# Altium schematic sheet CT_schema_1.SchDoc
size 544 x 512 mm
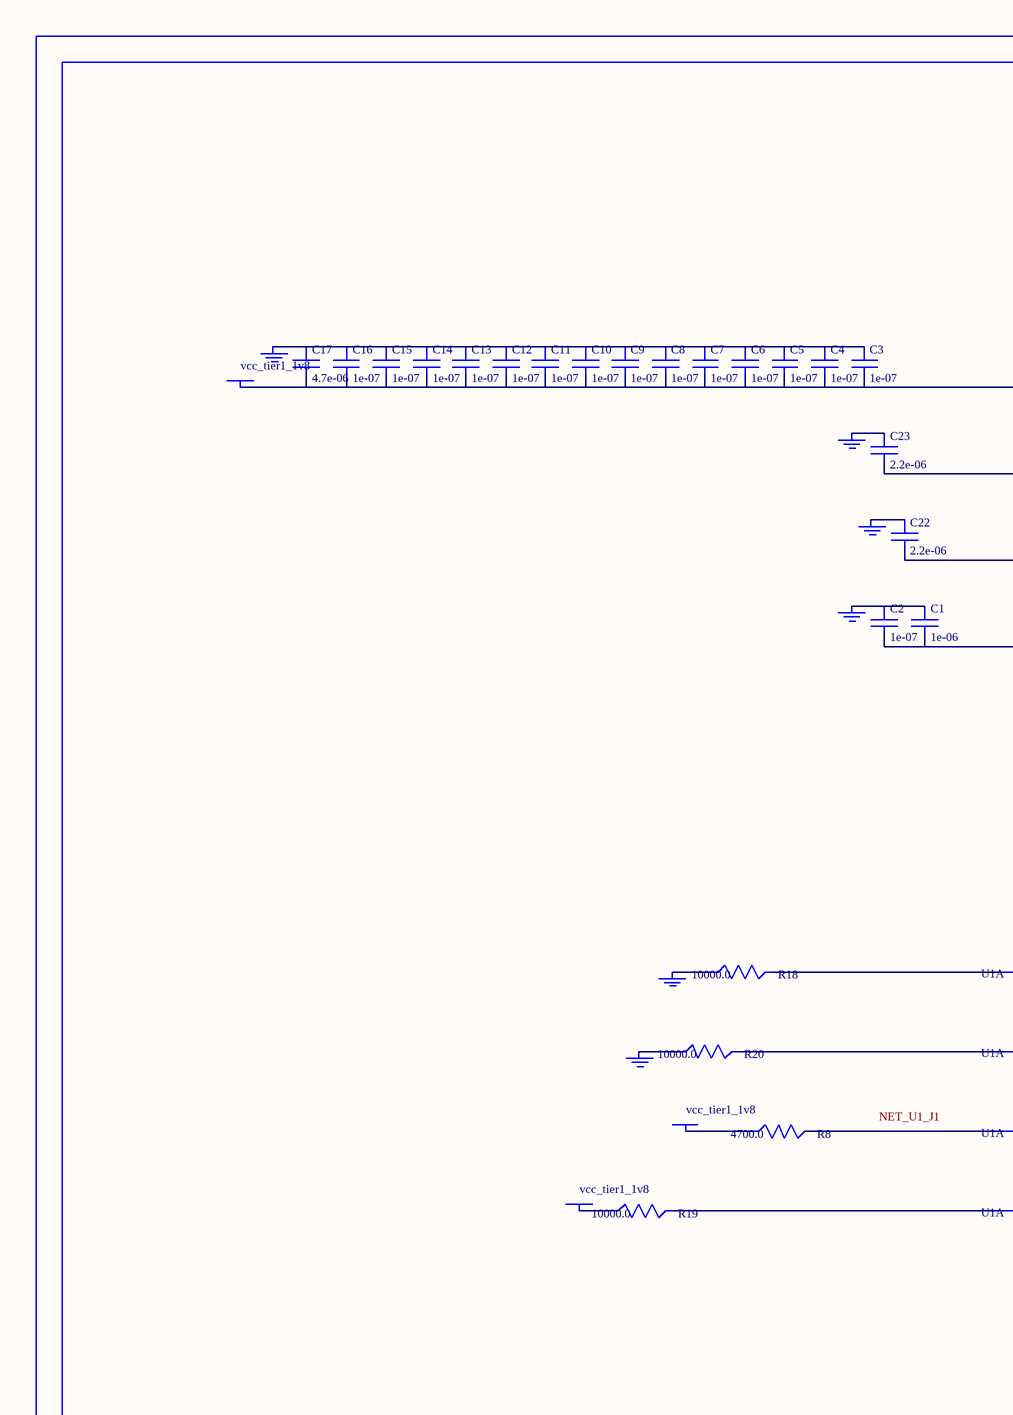
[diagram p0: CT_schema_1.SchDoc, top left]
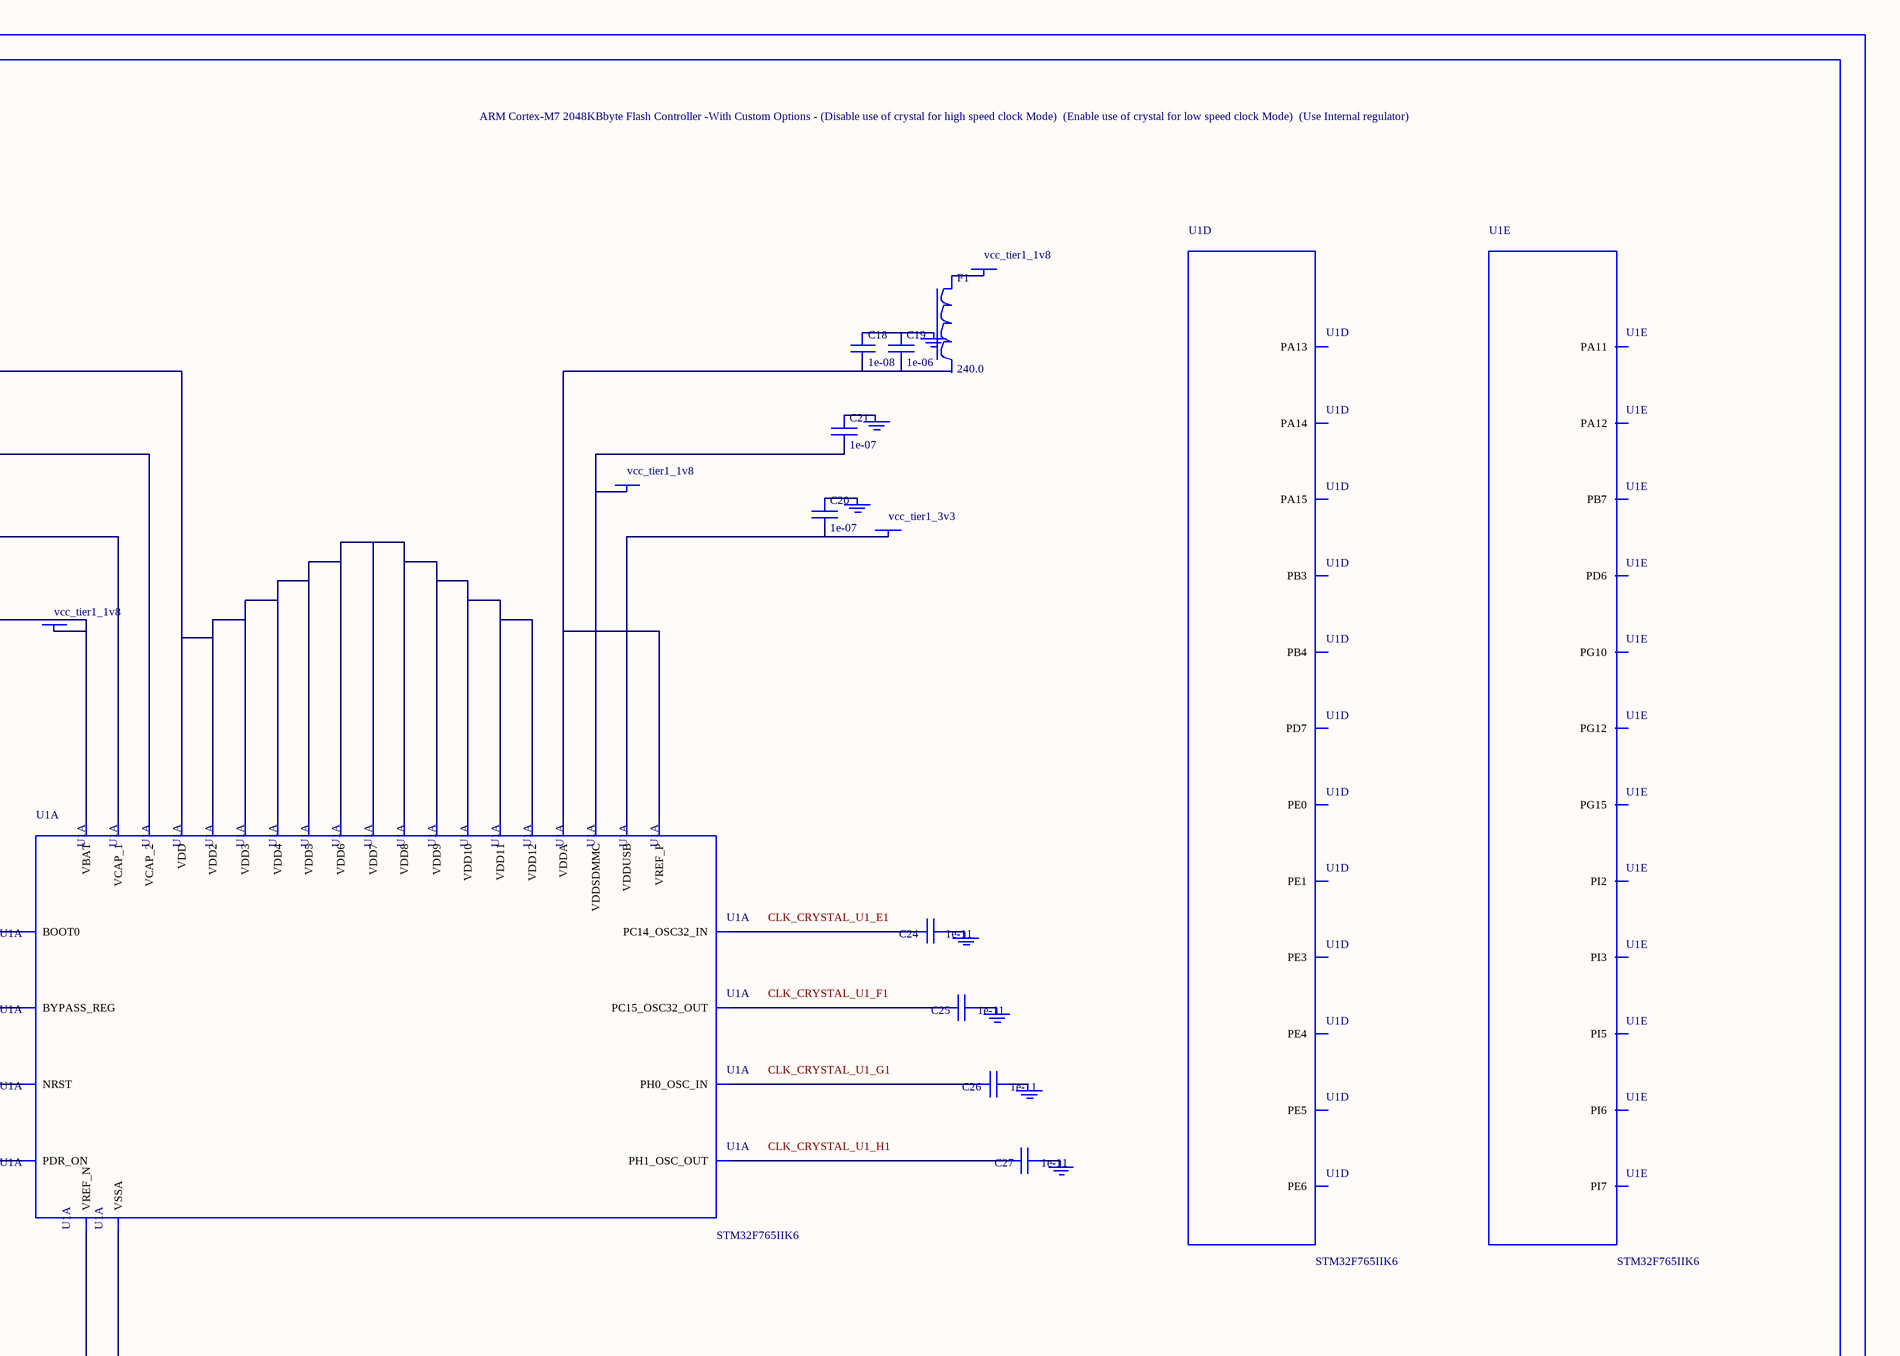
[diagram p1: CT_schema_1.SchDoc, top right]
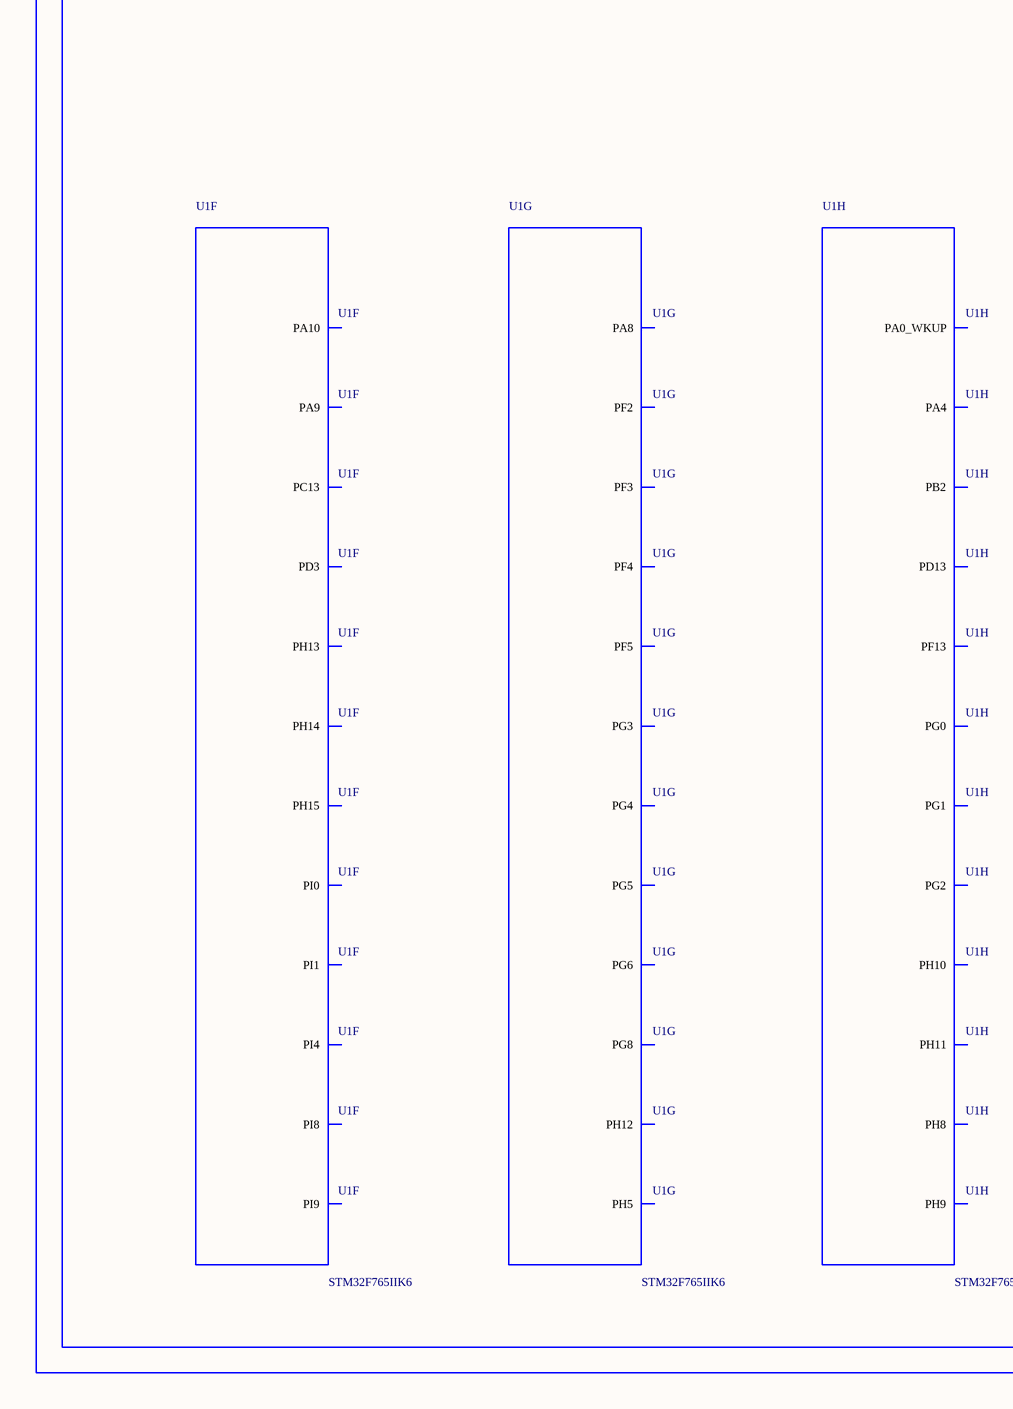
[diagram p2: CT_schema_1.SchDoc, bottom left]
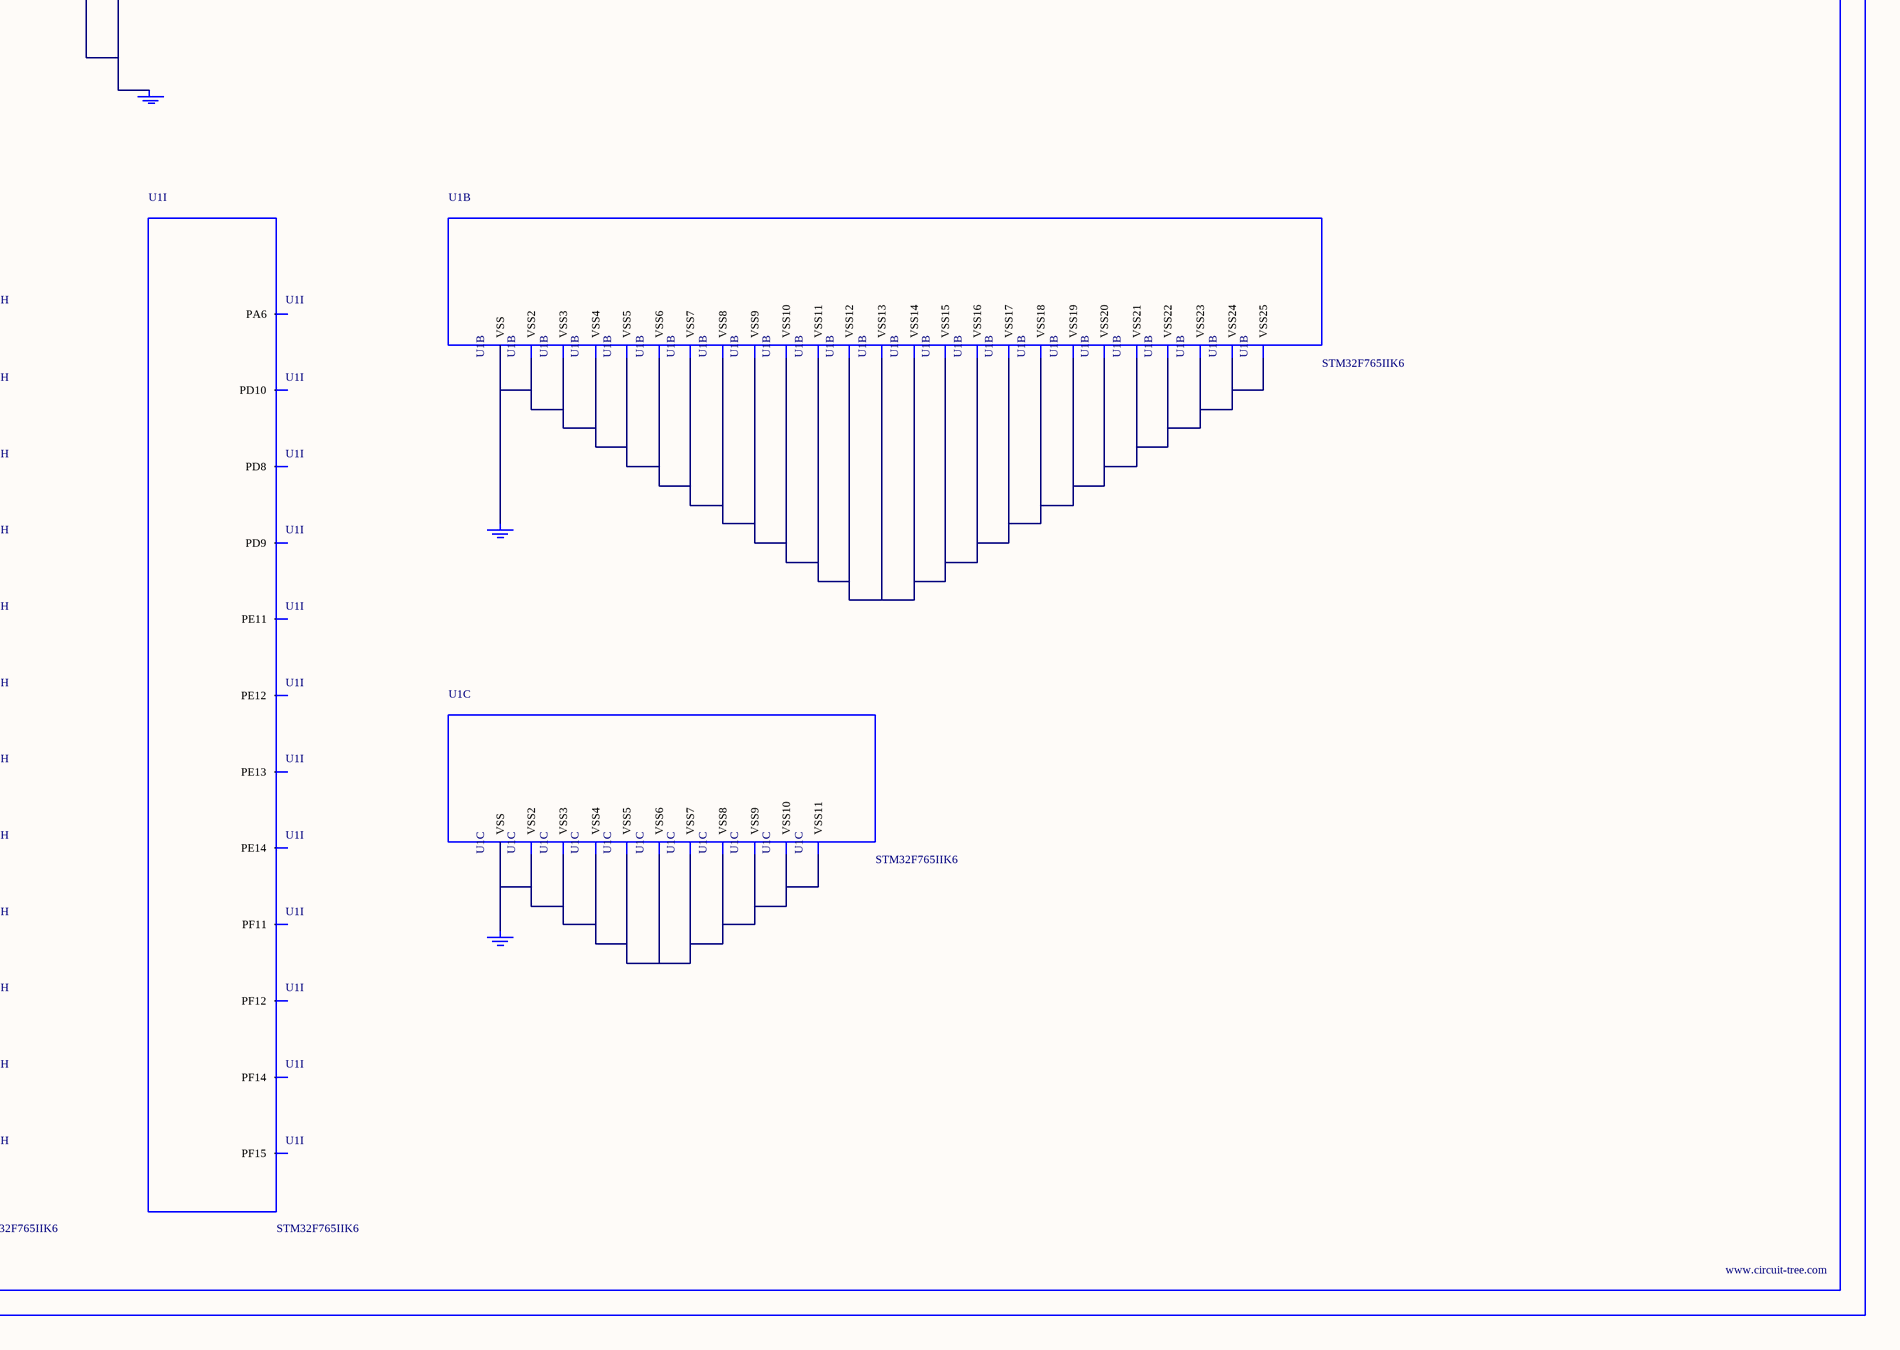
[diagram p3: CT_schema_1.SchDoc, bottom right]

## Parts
BORDER0  (no value)
C1  1e-06  [C0603]
C2  1e-07  [C0603]
C3  1e-07  [C0603]
C4  1e-07  [C0603]
C5  1e-07  [C0603]
C6  1e-07  [C0603]
C7  1e-07  [C0603]
C8  1e-07  [C0603]
C9  1e-07  [C0603]
C10  1e-07  [C0603]
C11  1e-07  [C0603]
C12  1e-07  [C0603]
C13  1e-07  [C0603]
C14  1e-07  [C0603]
C15  1e-07  [C0603]
C16  1e-07  [C0603]
C17  4.7e-06  [C0603]
C18  1e-08  [C0603]
C19  1e-06  [C0603]
C20  1e-07  [C0603]
C21  1e-07  [C0603]
C22  2.2e-06  [C0603]
C23  2.2e-06  [C0603]
C24  1e-11  [C0402]
C25  1e-11  [C0402]
C26  1e-11  [C0402]
C27  1e-11  [C0402]
F1  240.0  [L0603]
GND_INSTANCE_0_0  (no value)
GND_INSTANCE_0_1  (no value)
GND_INSTANCE_0_2  (no value)
GND_INSTANCE_0_3  (no value)
GND_INSTANCE_0_4  (no value)
GND_INSTANCE_0_5  (no value)
GND_INSTANCE_0_6  (no value)
GND_INSTANCE_0_7  (no value)
GND_INSTANCE_0_8  (no value)
GND_INSTANCE_0_9  (no value)
GND_INSTANCE_0_10  (no value)
GND_INSTANCE_0_11  (no value)
GND_INSTANCE_0_12  (no value)
GND_INSTANCE_0_13  (no value)
GND_INSTANCE_0_14  (no value)
GND_INSTANCE_0_15  (no value)
POWER_INSTANCE_0_0  vcc_tier1_1v8
POWER_INSTANCE_0_1  vcc_tier1_1v8
POWER_INSTANCE_0_2  vcc_tier1_1v8
POWER_INSTANCE_0_3  vcc_tier1_1v8
POWER_INSTANCE_0_4  vcc_tier1_3v3
POWER_INSTANCE_0_5  vcc_tier1_1v8
POWER_INSTANCE_0_6  vcc_tier1_1v8
R8  4700.0  [R0603]
R18  10000.0  [R0603]
R19  10000.0  [R0603]
R20  10000.0  [R0603]
U1  STM32F765IIK6  [UFBGA176_25]  (parts A,B,C,D,E,F,G,H,I of 17)

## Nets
NetC1_1: C1.1 C2.1 GND_INSTANCE_0_0.0(GND)
NetC1_2: C1.2 C2.2 POWER_INSTANCE_0_0.0(PWR) U1.C1(VBAT)
NetC3_1: C3.1 C4.1 C5.1 C6.1 C7.1 C8.1 C9.1 C10.1 C11.1 C12.1 C13.1 C14.1 C15.1 C16.1 C17.1 GND_INSTANCE_0_2.0(GND)
NetC3_2: C3.2 C4.2 C5.2 C6.2 C7.2 C8.2 C9.2 C10.2 C11.2 C12.2 C13.2 C14.2 C15.2 C16.2 C17.2 POWER_INSTANCE_0_2.0(PWR) U1.C5(VDD) U1.C7(VDD2) U1.C9(VDD3) U1.F3(VDD4) U1.G3(VDD6) U1.G13(VDD5) U1.J12(VDD7) U1.J13(VDD8) U1.K4(VDD9) U1.N8(VDD11) U1.N9(VDD12) U1.N10(VDD10)
NetC18_1: C18.1 C19.1 GND_INSTANCE_0_1.0(GND)
NetC18_2: C18.2 C19.2 U1.P1(VREF_P) U1.R1(VDDA)
NetC20_1: C20.1 GND_INSTANCE_0_4.0(GND)
NetC20_2: C20.2 POWER_INSTANCE_0_4.0(PWR) U1.H13(VDDUSB)
NetC21_1: C21.1 GND_INSTANCE_0_5.0(GND)
NetC21_2: C21.2 POWER_INSTANCE_0_5.0(PWR) U1.C8(VDDSDMMC)
NetC22_1: C22.1 GND_INSTANCE_0_7.0(GND)
NetC22_2: C22.2 U1.M10(VCAP_1)
NetC23_1: C23.1 GND_INSTANCE_0_8.0(GND)
NetC23_2: C23.2 U1.F13(VCAP_2)
NetC24_1: C24.1 GND_INSTANCE_0_9.0(GND)
NetC24_2: C24.2 U1.E1(PC14_OSC32_IN)
NetC25_1: C25.1 GND_INSTANCE_0_10.0(GND)
NetC25_2: C25.2 U1.F1(PC15_OSC32_OUT)
NetC26_1: C26.1 GND_INSTANCE_0_11.0(GND)
NetC26_2: C26.2 U1.G1(PH0_OSC_IN)
NetC27_1: C27.1 GND_INSTANCE_0_12.0(GND)
NetC27_2: C27.2 U1.H1(PH1_OSC_OUT)
NetF1_1: F1.1 POWER_INSTANCE_0_1.0(PWR)
NetGND_INSTANCE_0_3_0: GND_INSTANCE_0_3.0(GND) R18.1
NetGND_INSTANCE_0_6_0: GND_INSTANCE_0_6.0(GND) R20.1
NetGND_INSTANCE_0_13_0: GND_INSTANCE_0_13.0(GND) U1.M1(VSSA) U1.N1(VREF_N)
NetGND_INSTANCE_0_14_0: GND_INSTANCE_0_14.0(GND) U1.D5(VSS) U1.D7(VSS2) U1.D8(VSS3) U1.D9(VSS4) U1.F2(VSS7) U1.F6(VSS8) U1.F7(VSS9) U1.F8(VSS10) U1.F9(VSS11) U1.F10(VSS5) U1.F12(VSS6) U1.G2(VSS14) U1.G6(VSS15) U1.G7(VSS16) U1.G8(VSS17) U1.G9(VSS18) U1.G10(VSS12) U1.G12(VSS13) U1.H6(VSS21) U1.H7(VSS22) U1.H8(VSS23) U1.H9(VSS24) U1.H10(VSS19) U1.H12(VSS20) U1.J10(VSS25)
NetGND_INSTANCE_0_15_0: GND_INSTANCE_0_15.0(GND) U1.J6(VSS) U1.J7(VSS2) U1.J8(VSS3) U1.J9(VSS4) U1.K6(VSS6) U1.K7(VSS7) U1.K8(VSS8) U1.K9(VSS9) U1.K10(VSS5) U1.M8(VSS10) U1.M9(VSS11)
NetPOWER_INSTANCE_0_3_0: POWER_INSTANCE_0_3.0(PWR) R19.1
NetPOWER_INSTANCE_0_6_0: POWER_INSTANCE_0_6.0(PWR) R8.1
NetR8_2: R8.2 U1.J1(NRST)
NetR18_2: R18.2 U1.D6(BOOT0)
NetR19_2: R19.2 U1.C6(PDR_ON)
NetR20_2: R20.2 U1.L4(BYPASS_REG)

Not connected (* = marked no-connect by the designer): F1 2; U1 A1(PE3) A3(PE1) A4(PE0) A9(PB4) A10(PB3) A11(PD7) A13(PA15) A14(PA14) A15(PA13) B1(PE4) B2(PE5) B3(PE6) B5(PB7) B7(PG15) B8(PG12) B10(PG10) B11(PD6) B15(PA12) C2(PI7) C3(PI6) C4(PI5) C13(PI3) C14(PI2) C15(PA11) D1(PC13) D2(PI8) D3(PI9) D4(PI4) D11(PD3) D13(PH15) D14(PI1) D15(PA10) E12(PH13) E13(PH14) E14(PI0) E15(PA9) F15(PA8) H2(PF2) H14(PG8) J2(PF3) J3(PF4) J4(PH5) J15(PG6) K3(PF5) K12(PH12) K13(PG5) K14(PG4) K15(PG3) L12(PH11) L13(PH10) L15(PG2) M6(PB2) M7(PG1) M12(PH8) M13(PH9) M15(PD13) N3(PA0_WKUP) N4(PA4) N6(PF13) N7(PG0) N11(PE13) N15(PD10) P3(PA6) P6(PF12) P7(PF15) P10(PE11) P11(PE14) P14(PD9) P15(PD8) R6(PF11) R7(PF14) R10(PE12)

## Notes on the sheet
- Labels drawn without touching a wire or pin: CLK_CRYSTAL_U1_E1, CLK_CRYSTAL_U1_F1, CLK_CRYSTAL_U1_G1, CLK_CRYSTAL_U1_H1, NET_U1_J1

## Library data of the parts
BORDER0 = BORDER_PAGE0
C1 C19 = C0603C105K3RACTU
C2-C16 C20 C21 = 06035C104K4Z2A
C17 = GRM188R6YA475KE15D
C18 = 06035C103K4Z2A
C22 C23 = C0603C225K8RACTU
C24-C27 = C0402C100K3GACTU
F1 = Z0603C241ASMST
GND_INSTANCE_0_0-GND_INSTANCE_0_15 = GND
POWER_INSTANCE_0_0-POWER_INSTANCE_0_6 = PWR
R8 = RC0603JR-074K7L
R18-R20 = RC0603JR-0710KL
